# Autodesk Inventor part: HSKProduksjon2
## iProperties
Created: 2009-12
Part Number: HSKProduksjon2
Document SubType Name: Modeling
Designer: a31733
Density: 1 g/cm^3
Author: a31733
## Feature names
1. Circular Pattern1
2. Extrusion1
3. Loft1
4. Extrusion2
5. Extrusion4
6. Revolution1
7. Fillet5
8. Fillet6
9. Extrusion5
10. Fillet7
11. Extrusion6
12. Hole1
